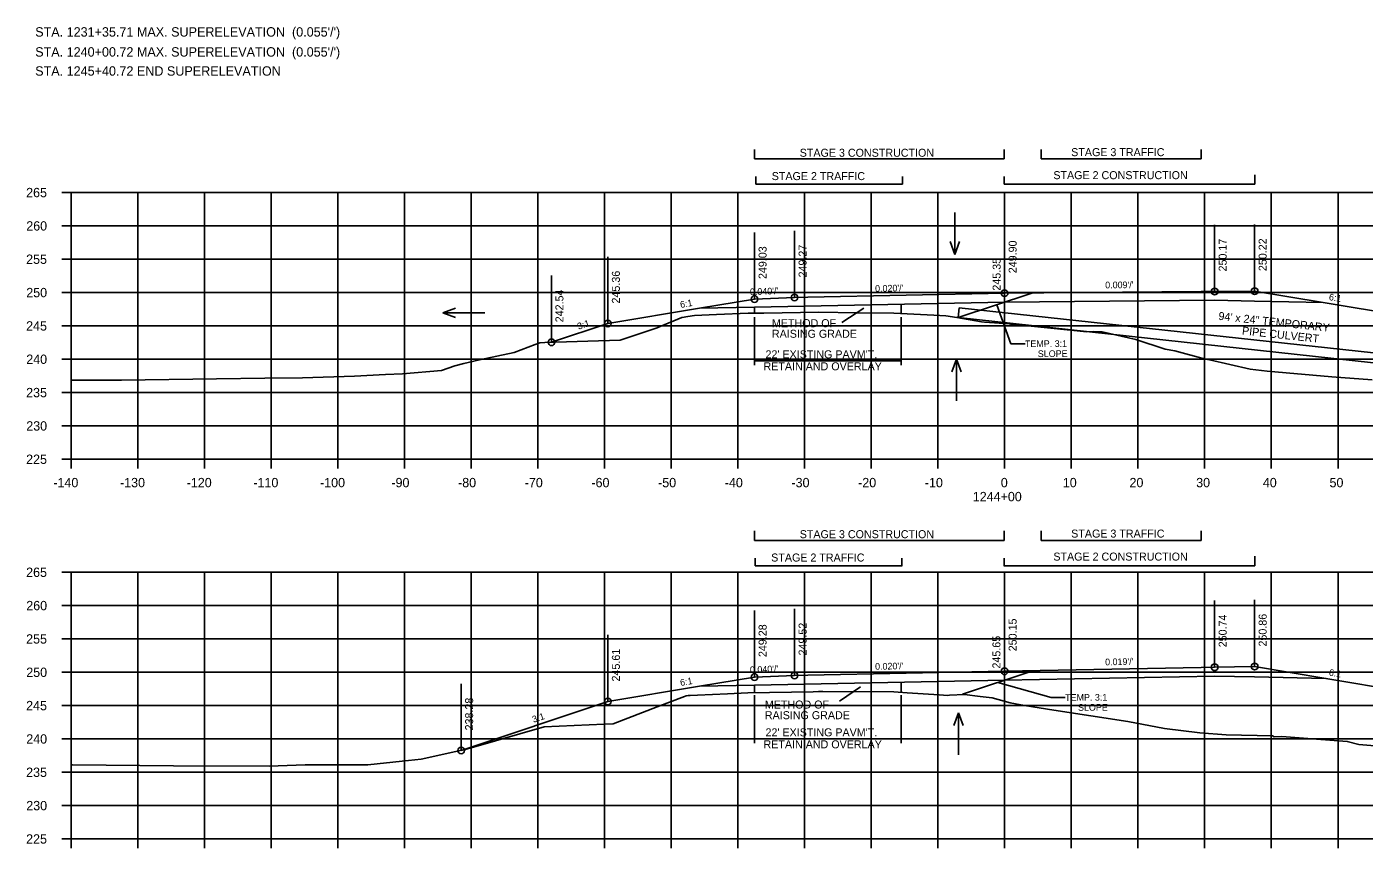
# Model space of a CAD drawing. Extents: x 1342547 to 1344156, y -1532351 to -1517216.
# Drawn here: x 1342556.2 to 1342756.8, y -1528435.2 to -1528312 of the extents above; entities that cross this region are included whole.
import ezdxf

# ---------------------------------------------------------------- set-up
doc = ezdxf.new("R2010")
doc.units = 0
for name, color, linetype in [('R_Alt Surface', 7, 'Continuous'), ('R_Axis', 7, 'Continuous'), ('R_Axis Annot', 7, 'Continuous'), ('R_Border Notes', 7, 'Continuous'), ('R_Draft', 7, 'Continuous'), ('R_Exist Surface', 7, 'Continuous'), ('R_Fin Surface', 7, 'Continuous'), ('R_Grid', 7, 'Continuous'), ('R_No Plot', 7, 'Continuous'), ('R_Water', 7, 'Continuous'), ('R_Xsect Elev', 7, 'Continuous'), ('R_Xsect Slope', 7, 'Continuous')]:
    doc.layers.add(name, color=color, linetype=linetype)

msp = doc.modelspace()

# ---------------------------------------------------------------- linework, layer by layer
at = {"layer": 'R_Alt Surface'}
for points in [[(1342740.37, -1528353.13), (1342734.37, -1528353.01), (1342702.87, -1528353.29)], [(1342740.37, -1528353.13), (1342750.63, -1528353.34)], [(1342657.09, -1528354.2), (1342665.37, -1528354.04)], [(1342665.37, -1528354.04), (1342702.87, -1528353.29)], [(1342657.09, -1528410.9), (1342665.37, -1528410.73)], [(1342665.37, -1528410.73), (1342702.87, -1528409.98)], [(1342740.37, -1528409.51), (1342734.37, -1528409.39), (1342702.87, -1528409.98)], [(1342740.37, -1528409.51), (1342751.05, -1528409.72)]]:
    msp.add_lwpolyline(points, dxfattribs=at)
at = {"layer": 'R_Axis'}
for p, q in [((1342561.47, -1528336.85), (1342562.87, -1528336.85)), ((1342562.87, -1528376.85), (1342562.87, -1528336.85)), ((1342561.47, -1528341.85), (1342562.87, -1528341.85)), ((1342561.47, -1528346.85), (1342562.87, -1528346.85)), ((1342561.47, -1528351.85), (1342562.87, -1528351.85)), ((1342561.47, -1528356.85), (1342562.87, -1528356.85)), ((1342561.47, -1528361.85), (1342562.87, -1528361.85)), ((1342561.47, -1528366.85), (1342562.87, -1528366.85)), ((1342561.47, -1528371.85), (1342562.87, -1528371.85)), ((1342561.47, -1528376.85), (1342562.87, -1528376.85)), ((1342562.87, -1528376.85), (1342842.87, -1528376.85)), ((1342562.87, -1528378.25), (1342562.87, -1528376.85)), ((1342572.87, -1528378.25), (1342572.87, -1528376.85)), ((1342582.87, -1528378.25), (1342582.87, -1528376.85)), ((1342592.87, -1528378.25), (1342592.87, -1528376.85)), ((1342602.87, -1528378.25), (1342602.87, -1528376.85)), ((1342612.87, -1528378.25), (1342612.87, -1528376.85)), ((1342622.87, -1528378.25), (1342622.87, -1528376.85)), ((1342632.87, -1528378.25), (1342632.87, -1528376.85)), ((1342642.87, -1528378.25), (1342642.87, -1528376.85)), ((1342652.87, -1528378.25), (1342652.87, -1528376.85)), ((1342662.87, -1528378.25), (1342662.87, -1528376.85)), ((1342672.87, -1528378.25), (1342672.87, -1528376.85)), ((1342682.87, -1528378.25), (1342682.87, -1528376.85)), ((1342692.87, -1528378.25), (1342692.87, -1528376.85)), ((1342702.87, -1528378.25), (1342702.87, -1528376.85)), ((1342712.87, -1528378.25), (1342712.87, -1528376.85)), ((1342722.87, -1528378.25), (1342722.87, -1528376.85)), ((1342732.87, -1528378.25), (1342732.87, -1528376.85)), ((1342742.87, -1528378.25), (1342742.87, -1528376.85)), ((1342752.87, -1528378.25), (1342752.87, -1528376.85)), ((1342561.47, -1528393.8), (1342562.87, -1528393.8)), ((1342562.87, -1528433.8), (1342562.87, -1528393.8)), ((1342561.47, -1528398.8), (1342562.87, -1528398.8)), ((1342561.47, -1528403.8), (1342562.87, -1528403.8)), ((1342561.47, -1528408.8), (1342562.87, -1528408.8)), ((1342561.47, -1528413.8), (1342562.87, -1528413.8)), ((1342561.47, -1528418.8), (1342562.87, -1528418.8)), ((1342561.47, -1528423.8), (1342562.87, -1528423.8)), ((1342561.47, -1528428.8), (1342562.87, -1528428.8)), ((1342561.47, -1528433.8), (1342562.87, -1528433.8)), ((1342562.87, -1528433.8), (1342842.87, -1528433.8)), ((1342562.87, -1528435.2), (1342562.87, -1528433.8)), ((1342572.87, -1528435.2), (1342572.87, -1528433.8)), ((1342582.87, -1528435.2), (1342582.87, -1528433.8)), ((1342592.87, -1528435.2), (1342592.87, -1528433.8)), ((1342602.87, -1528435.2), (1342602.87, -1528433.8)), ((1342612.87, -1528435.2), (1342612.87, -1528433.8)), ((1342622.87, -1528435.2), (1342622.87, -1528433.8)), ((1342632.87, -1528435.2), (1342632.87, -1528433.8)), ((1342642.87, -1528435.2), (1342642.87, -1528433.8)), ((1342652.87, -1528435.2), (1342652.87, -1528433.8)), ((1342662.87, -1528435.2), (1342662.87, -1528433.8)), ((1342672.87, -1528435.2), (1342672.87, -1528433.8)), ((1342682.87, -1528435.2), (1342682.87, -1528433.8)), ((1342692.87, -1528435.2), (1342692.87, -1528433.8)), ((1342702.87, -1528435.2), (1342702.87, -1528433.8)), ((1342712.87, -1528435.2), (1342712.87, -1528433.8)), ((1342722.87, -1528435.2), (1342722.87, -1528433.8)), ((1342732.87, -1528435.2), (1342732.87, -1528433.8)), ((1342742.87, -1528435.2), (1342742.87, -1528433.8)), ((1342752.87, -1528435.2), (1342752.87, -1528433.8))]:
    msp.add_line(p, q, dxfattribs=at)
at = {"layer": 'R_Draft'}
for p, q in [((1342665.37, -1528331.81), (1342665.37, -1528330.38)), ((1342702.78, -1528331.81), (1342702.78, -1528330.38)), ((1342708.37, -1528331.81), (1342708.37, -1528330.38)), ((1342732.37, -1528331.81), (1342732.37, -1528330.38)), ((1342665.37, -1528331.81), (1342702.78, -1528331.81)), ((1342708.37, -1528331.81), (1342732.37, -1528331.81)), ((1342665.54, -1528335.6), (1342665.54, -1528334.46)), ((1342687.54, -1528335.6), (1342687.54, -1528334.46)), ((1342702.78, -1528335.6), (1342702.78, -1528334.46)), ((1342740.38, -1528335.6), (1342740.38, -1528334.17)), ((1342665.54, -1528335.6), (1342687.54, -1528335.6)), ((1342702.78, -1528335.6), (1342740.38, -1528335.6)), ((1342665.37, -1528354.04), (1342665.37, -1528354.94)), ((1342687.37, -1528353.61), (1342687.37, -1528354.96)), ((1342665.37, -1528355.55), (1342665.37, -1528362.75)), ((1342687.37, -1528355.55), (1342687.37, -1528362.75)), ((1342665.37, -1528362.08), (1342687.37, -1528362.08)), ((1342665.37, -1528389.02), (1342665.37, -1528387.59)), ((1342665.37, -1528389.02), (1342702.78, -1528389.02)), ((1342702.78, -1528389.02), (1342702.78, -1528387.59)), ((1342708.37, -1528389.02), (1342708.37, -1528387.59)), ((1342708.37, -1528389.02), (1342732.37, -1528389.02)), ((1342732.37, -1528389.02), (1342732.37, -1528387.59)), ((1342665.45, -1528392.82), (1342665.45, -1528391.67)), ((1342665.45, -1528392.82), (1342687.46, -1528392.82)), ((1342687.46, -1528392.91), (1342687.46, -1528391.67)), ((1342702.78, -1528392.91), (1342702.78, -1528391.67)), ((1342702.78, -1528392.82), (1342740.38, -1528392.82)), ((1342740.38, -1528392.82), (1342740.38, -1528391.38)), ((1342665.37, -1528410.73), (1342665.37, -1528411.88)), ((1342687.37, -1528410.31), (1342687.37, -1528411.81)), ((1342665.37, -1528412.25), (1342665.37, -1528419.44)), ((1342687.37, -1528412.25), (1342687.37, -1528419.44)), ((1342665.37, -1528418.77), (1342687.37, -1528418.77))]:
    msp.add_line(p, q, dxfattribs=at)
at = {"layer": 'R_Exist Surface'}
for points in [[(1342562.87, -1528364.99), (1342570.4, -1528364.98), (1342584.66, -1528364.79), (1342591.9, -1528364.68), (1342597.55, -1528364.62), (1342605.35, -1528364.41), (1342610.04, -1528364.14), (1342612.57, -1528364.03), (1342618.43, -1528363.52), (1342620.41, -1528362.85), (1342621.74, -1528362.48), (1342624.11, -1528361.96), (1342629.3, -1528360.82), (1342632.46, -1528359.64), (1342633.14, -1528359.38), (1342633.92, -1528359.35), (1342645.19, -1528358.97), (1342650.33, -1528357.28), (1342650.77, -1528357.15), (1342651.2, -1528356.96), (1342654.46, -1528355.57), (1342654.82, -1528355.53), (1342655.05, -1528355.49), (1342656.03, -1528355.33), (1342656.34, -1528355.28), (1342659.68, -1528355.14), (1342664.42, -1528354.95), (1342666.75, -1528354.92), (1342674.99, -1528354.8), (1342680.74, -1528354.88), (1342686.27, -1528354.94), (1342692.23, -1528355.25), (1342694.06, -1528355.35), (1342695.71, -1528355.58), (1342699.4, -1528356.23), (1342699.87, -1528356.27), (1342703.57, -1528356.56), (1342703.77, -1528356.58), (1342703.88, -1528356.57), (1342715.21, -1528357.73), (1342716.25, -1528357.67), (1342717.52, -1528357.75), (1342722.56, -1528358.91), (1342726.97, -1528360.32), (1342728.39, -1528360.6), (1342733, -1528361.82), (1342733.61, -1528361.96), (1342739.7, -1528363.32), (1342742.25, -1528363.66), (1342751.95, -1528364.49), (1342757.98, -1528364.92)], [(1342562.87, -1528422.7), (1342563.07, -1528422.7), (1342578.21, -1528422.82), (1342592.55, -1528422.9), (1342597.96, -1528422.69), (1342607.38, -1528422.69), (1342612.53, -1528422.15), (1342615.34, -1528421.83), (1342621.89, -1528420.4), (1342622, -1528420.37), (1342622.13, -1528420.34), (1342622.85, -1528420.14), (1342633.8, -1528416.98), (1342642.79, -1528416.56), (1342644.17, -1528416.53), (1342650.77, -1528413.98), (1342654.88, -1528412.43), (1342655.13, -1528412.32), (1342655.39, -1528412.3), (1342655.71, -1528412.28), (1342656.79, -1528412.22), (1342661.32, -1528412.02), (1342664.38, -1528411.89), (1342674.16, -1528411.71), (1342674.98, -1528411.7), (1342675.61, -1528411.7), (1342686.24, -1528411.73), (1342688.25, -1528411.87), (1342693.07, -1528412.19), (1342694.36, -1528412.28), (1342694.61, -1528412.24), (1342696.86, -1528412.13), (1342699.22, -1528412.43), (1342701, -1528412.64), (1342703.72, -1528413.38), (1342705.84, -1528413.79), (1342710.25, -1528414.5), (1342721.37, -1528416.2), (1342726.86, -1528417.24), (1342726.87, -1528417.25), (1342732.14, -1528417.89), (1342736.1, -1528418.17), (1342743.06, -1528418.34), (1342743.32, -1528418.48), (1342744.45, -1528418.42), (1342747.02, -1528418.65), (1342754.26, -1528419.17), (1342755.99, -1528419.62), (1342758.39, -1528419.82)]]:
    msp.add_lwpolyline(points, dxfattribs=at)
at = {"layer": 'R_Fin Surface'}
for p, q in [((1342695.89, -1528355.61), (1342706.97, -1528351.92)), ((1342696.55, -1528412.09), (1342707.1, -1528408.57))]:
    msp.add_line(p, q, dxfattribs=at)
for points in [[(1342634.9, -1528359.31), (1342643.37, -1528356.49), (1342657.09, -1528354.2), (1342665.37, -1528352.82), (1342671.37, -1528352.58), (1342673.37, -1528352.54), (1342702.87, -1528351.95), (1342732.37, -1528351.7), (1342734.37, -1528351.68), (1342740.37, -1528351.63), (1342750.63, -1528353.34), (1342762.37, -1528355.3), (1342793.9, -1528365.81)], [(1342621.36, -1528420.52), (1342643.37, -1528413.18), (1342657.09, -1528410.9), (1342665.37, -1528409.52), (1342671.37, -1528409.28), (1342673.37, -1528409.24), (1342702.87, -1528408.65), (1342732.37, -1528408.09), (1342734.37, -1528408.05), (1342740.37, -1528407.94), (1342751.05, -1528409.72), (1342762.37, -1528411.61), (1342795.36, -1528422.6)]]:
    msp.add_lwpolyline(points, dxfattribs=at)
at = {"layer": 'R_Grid'}
for p, q in [((1342562.87, -1528336.85), (1342842.87, -1528336.85)), ((1342562.87, -1528376.85), (1342562.87, -1528336.85)), ((1342572.87, -1528376.85), (1342572.87, -1528336.85)), ((1342582.87, -1528376.85), (1342582.87, -1528336.85)), ((1342592.87, -1528376.85), (1342592.87, -1528336.85)), ((1342602.87, -1528376.85), (1342602.87, -1528336.85)), ((1342612.87, -1528376.85), (1342612.87, -1528336.85)), ((1342622.87, -1528376.85), (1342622.87, -1528336.85)), ((1342632.87, -1528376.85), (1342632.87, -1528336.85)), ((1342642.87, -1528376.85), (1342642.87, -1528336.85)), ((1342652.87, -1528376.85), (1342652.87, -1528336.85)), ((1342662.87, -1528376.85), (1342662.87, -1528336.85)), ((1342672.87, -1528376.85), (1342672.87, -1528336.85)), ((1342682.87, -1528376.85), (1342682.87, -1528336.85)), ((1342692.87, -1528376.85), (1342692.87, -1528336.85)), ((1342702.87, -1528376.85), (1342702.87, -1528336.85)), ((1342712.87, -1528376.85), (1342712.87, -1528336.85)), ((1342722.87, -1528376.85), (1342722.87, -1528336.85)), ((1342732.87, -1528376.85), (1342732.87, -1528336.85)), ((1342742.87, -1528376.85), (1342742.87, -1528336.85)), ((1342752.87, -1528376.85), (1342752.87, -1528336.85)), ((1342562.87, -1528341.85), (1342842.87, -1528341.85)), ((1342562.87, -1528346.85), (1342842.87, -1528346.85)), ((1342562.87, -1528351.85), (1342842.87, -1528351.85)), ((1342562.87, -1528356.85), (1342842.87, -1528356.85)), ((1342562.87, -1528361.85), (1342842.87, -1528361.85)), ((1342562.87, -1528366.85), (1342842.87, -1528366.85)), ((1342562.87, -1528371.85), (1342842.87, -1528371.85)), ((1342562.87, -1528376.85), (1342842.87, -1528376.85)), ((1342562.87, -1528393.8), (1342842.87, -1528393.8)), ((1342562.87, -1528433.8), (1342562.87, -1528393.8)), ((1342572.87, -1528433.8), (1342572.87, -1528393.8)), ((1342582.87, -1528433.8), (1342582.87, -1528393.8)), ((1342592.87, -1528433.8), (1342592.87, -1528393.8)), ((1342602.87, -1528433.8), (1342602.87, -1528393.8)), ((1342612.87, -1528433.8), (1342612.87, -1528393.8)), ((1342622.87, -1528433.8), (1342622.87, -1528393.8)), ((1342632.87, -1528433.8), (1342632.87, -1528393.8)), ((1342642.87, -1528433.8), (1342642.87, -1528393.8)), ((1342652.87, -1528433.8), (1342652.87, -1528393.8)), ((1342662.87, -1528433.8), (1342662.87, -1528393.8)), ((1342672.87, -1528433.8), (1342672.87, -1528393.8)), ((1342682.87, -1528433.8), (1342682.87, -1528393.8)), ((1342692.87, -1528433.8), (1342692.87, -1528393.8)), ((1342702.87, -1528433.8), (1342702.87, -1528393.8)), ((1342712.87, -1528433.8), (1342712.87, -1528393.8)), ((1342722.87, -1528433.8), (1342722.87, -1528393.8)), ((1342732.87, -1528433.8), (1342732.87, -1528393.8)), ((1342742.87, -1528433.8), (1342742.87, -1528393.8)), ((1342752.87, -1528433.8), (1342752.87, -1528393.8)), ((1342562.87, -1528398.8), (1342842.87, -1528398.8)), ((1342562.87, -1528403.8), (1342842.87, -1528403.8)), ((1342562.87, -1528408.8), (1342842.87, -1528408.8)), ((1342562.87, -1528413.8), (1342842.87, -1528413.8)), ((1342562.87, -1528418.8), (1342842.87, -1528418.8)), ((1342562.87, -1528423.8), (1342842.87, -1528423.8)), ((1342562.87, -1528428.8), (1342842.87, -1528428.8)), ((1342562.87, -1528433.8), (1342842.87, -1528433.8))]:
    msp.add_line(p, q, dxfattribs=at)
at = {"layer": 'R_No Plot'}
for centre in [(1342734.37, -1528351.68), (1342740.37, -1528351.63), (1342665.37, -1528352.82), (1342671.37, -1528352.58), (1342702.87, -1528351.95), (1342643.37, -1528356.49), (1342634.9, -1528359.31), (1342665.37, -1528409.52), (1342671.37, -1528409.28), (1342702.87, -1528408.65), (1342734.37, -1528408.05), (1342740.37, -1528407.94), (1342643.37, -1528413.18), (1342621.36, -1528420.52)]:
    msp.add_circle(centre, 0.5, dxfattribs=at)
at = {"layer": 'R_Water'}
for p, q in [((1342695.41, -1528339.85), (1342695.41, -1528346.13)), ((1342695.41, -1528346.13), (1342694.71, -1528344.21)), ((1342695.41, -1528346.13), (1342696.11, -1528344.21)), ((1342618.61, -1528354.87), (1342620.53, -1528354.17)), ((1342624.89, -1528354.87), (1342618.61, -1528354.87)), ((1342618.61, -1528354.87), (1342620.53, -1528355.57)), ((1342695.67, -1528361.82), (1342694.97, -1528363.74)), ((1342695.67, -1528368.1), (1342695.67, -1528361.82)), ((1342695.67, -1528361.82), (1342696.37, -1528363.74)), ((1342695.97, -1528414.88), (1342695.27, -1528416.8)), ((1342695.97, -1528421.16), (1342695.97, -1528414.88)), ((1342695.97, -1528414.88), (1342696.67, -1528416.8))]:
    msp.add_line(p, q, dxfattribs=at)
for points in [[(1342696.05, -1528354.12), (1342695.89, -1528355.61)], [(1342696.05, -1528354.12), (1342789.06, -1528364.23)], [(1342695.89, -1528355.61), (1342788.9, -1528365.72)]]:
    msp.add_lwpolyline(points, dxfattribs=at)
at = {"layer": 'R_Xsect Elev'}
for p, q in [((1342665.37, -1528352.82), (1342665.37, -1528342.82)), ((1342671.37, -1528352.58), (1342671.37, -1528342.58)), ((1342702.87, -1528351.95), (1342702.87, -1528341.95)), ((1342734.37, -1528351.68), (1342734.37, -1528341.68)), ((1342740.37, -1528351.63), (1342740.37, -1528341.63)), ((1342643.37, -1528356.49), (1342643.37, -1528346.49)), ((1342702.87, -1528356.5), (1342702.87, -1528346.5)), ((1342634.9, -1528359.31), (1342634.9, -1528349.31)), ((1342678.47, -1528356.33), (1342681.76, -1528354.21)), ((1342701.69, -1528353.68), (1342703.8, -1528359.53)), ((1342703.8, -1528359.53), (1342705.94, -1528359.53)), ((1342671.37, -1528409.28), (1342671.37, -1528399.28)), ((1342702.87, -1528408.65), (1342702.87, -1528398.65)), ((1342734.37, -1528408.05), (1342734.37, -1528398.05)), ((1342740.37, -1528407.94), (1342740.37, -1528397.94)), ((1342665.37, -1528409.52), (1342665.37, -1528399.52)), ((1342643.37, -1528413.18), (1342643.37, -1528403.18)), ((1342702.87, -1528413.15), (1342702.87, -1528403.15)), ((1342621.36, -1528420.52), (1342621.36, -1528410.52)), ((1342681.23, -1528410.99), (1342678.08, -1528413.11)), ((1342701.84, -1528410.32), (1342709.83, -1528412.58)), ((1342709.83, -1528412.58), (1342711.97, -1528412.58))]:
    msp.add_line(p, q, dxfattribs=at)

# ---------------------------------------------------------------- texts
at = {"layer": 'R_Axis Annot'}
for s, p in [('265', (1342556.12, -1528337.55)), ('260', (1342556.14, -1528342.55)), ('255', (1342556.12, -1528347.55)), ('250', (1342556.14, -1528352.55)), ('245', (1342556.12, -1528357.55)), ('240', (1342556.14, -1528362.55)), ('235', (1342556.12, -1528367.55)), ('230', (1342556.14, -1528372.55)), ('225', (1342556.12, -1528377.55)), ('-140', (1342560.2, -1528381.05)), ('-130', (1342570.2, -1528381.05)), ('-120', (1342580.2, -1528381.05)), ('-110', (1342590.2, -1528381.05)), ('-100', (1342600.2, -1528381.05)), ('-90', (1342610.9, -1528381.05)), ('-80', (1342620.9, -1528381.05)), ('-70', (1342630.9, -1528381.05)), ('-60', (1342640.9, -1528381.05)), ('-50', (1342650.9, -1528381.05)), ('-40', (1342660.9, -1528381.05)), ('-30', (1342670.9, -1528381.05)), ('-20', (1342680.9, -1528381.05)), ('-10', (1342690.9, -1528381.05)), ('0', (1342702.3, -1528381.05)), ('10', (1342711.6, -1528381.05)), ('20', (1342721.6, -1528381.05)), ('30', (1342731.6, -1528381.05)), ('40', (1342741.6, -1528381.05)), ('50', (1342751.6, -1528381.05)), ('1244+00', (1342698.1, -1528383.15)), ('265', (1342556.12, -1528394.5)), ('260', (1342556.14, -1528399.5)), ('255', (1342556.12, -1528404.5)), ('250', (1342556.14, -1528409.5)), ('245', (1342556.12, -1528414.5)), ('240', (1342556.14, -1528419.5)), ('235', (1342556.12, -1528424.5)), ('230', (1342556.14, -1528429.5)), ('225', (1342556.12, -1528434.5))]:
    msp.add_text(s, height=1.4, dxfattribs=at).set_placement(p)
at = {"layer": 'R_Border Notes'}
for s, p in [("STA. 1231+35.71 MAX. SUPERELEVATION  (0.055'/')", (1342557.48, -1528313.46)), ("STA. 1240+00.72 MAX. SUPERELEVATION  (0.055'/')", (1342557.48, -1528316.46)), ('STA. 1245+40.72 END SUPERELEVATION', (1342557.48, -1528319.32))]:
    msp.add_text(s, height=1.41, dxfattribs=at).set_placement(p)
at = {"layer": 'R_Draft'}
for s, p in [('STAGE 3 CONSTRUCTION', (1342672.14, -1528331.48)), ('STAGE 3 TRAFFIC', (1342712.85, -1528331.39)), ('STAGE 2 TRAFFIC', (1342667.94, -1528334.98)), ('STAGE 2 CONSTRUCTION', (1342710.18, -1528334.84)), ("22' EXISTING PAVM'T.", (1342667.01, -1528361.71)), ('RETAIN AND OVERLAY', (1342666.71, -1528363.51)), ('STAGE 3 CONSTRUCTION', (1342672.14, -1528388.69)), ('STAGE 3 TRAFFIC', (1342712.85, -1528388.6)), ('STAGE 2 TRAFFIC', (1342667.86, -1528392.19)), ('STAGE 2 CONSTRUCTION', (1342710.18, -1528392.05)), ("22' EXISTING PAVM'T.", (1342667.01, -1528418.41)), ('RETAIN AND OVERLAY', (1342666.71, -1528420.21))]:
    msp.add_text(s, height=1.2, dxfattribs=at).set_placement(p)
at = {"layer": 'R_Water'}
for s, p in [('94\' x 24" TEMPORARY', (1342734.89, -1528355.93)), ('PIPE CULVERT', (1342738.43, -1528358.13))]:
    msp.add_text(s, height=1.2, rotation=353.7979, dxfattribs=at).set_placement(p)
at = {"layer": 'R_Xsect Elev'}
for s, p in [('249.03', (1342667.17, -1528349.82)), ('249.27', (1342673.17, -1528349.58)), ('249.90', (1342704.67, -1528348.95)), ('250.17', (1342736.17, -1528348.68)), ('250.22', (1342742.17, -1528348.63)), ('245.35', (1342702.27, -1528351.56)), ('245.36', (1342645.17, -1528353.49)), ('242.54', (1342636.7, -1528356.31)), ('250.15', (1342704.67, -1528405.65)), ('250.74', (1342736.17, -1528405.05)), ('250.86', (1342742.17, -1528404.94)), ('249.28', (1342667.17, -1528406.52)), ('249.52', (1342673.17, -1528406.28)), ('245.61', (1342645.17, -1528410.18)), ('245.65', (1342702.24, -1528408.24)), ('238.28', (1342623.16, -1528417.52))]:
    msp.add_text(s, height=1.2, rotation=90, dxfattribs=at).set_placement(p)
for s, p in [('METHOD OF', (1342667.97, -1528357.04)), ('RAISING GRADE', (1342667.97, -1528358.63)), ('METHOD OF', (1342666.91, -1528414.24)), ('RAISING GRADE', (1342666.91, -1528415.84))]:
    msp.add_text(s, height=1.2, dxfattribs=at).set_placement(p)
at = {"layer": 'R_Xsect Slope'}
for s, rotation, p in [("0.040'/'", 2.2906, (1342664.69, -1528352.25)), ("0.020'/'", 1.1458, (1342683.45, -1528351.74)), ("0.009'/'", 0.4965, (1342717.96, -1528351.22)), ('6:1', 9.4623, (1342654.28, -1528354.16)), ('6:1', 350.5377, (1342751.45, -1528352.97)), ('3:1', 18.4349, (1342638.97, -1528357.43)), ('TEMP. 3:1', 0.3758, (1342705.92, -1528360.04)), ('SLOPE', 0.3758, (1342707.85, -1528361.53)), ("0.020'/'", 1.1458, (1342683.45, -1528408.43)), ("0.019'/'", 1.0799, (1342717.95, -1528407.76)), ("0.040'/'", 2.2906, (1342664.69, -1528408.94)), ('6:1', 350.5377, (1342751.45, -1528409.28)), ('6:1', 9.4623, (1342654.28, -1528410.86)), ('TEMP. 3:1', 0.3758, (1342711.95, -1528413.09)), ('3:1', 18.4349, (1342632.21, -1528416.38)), ('SLOPE', 0.3758, (1342713.88, -1528414.58))]:
    msp.add_text(s, height=1, rotation=rotation, dxfattribs=at).set_placement(p)

doc.saveas('drawing.dxf')
